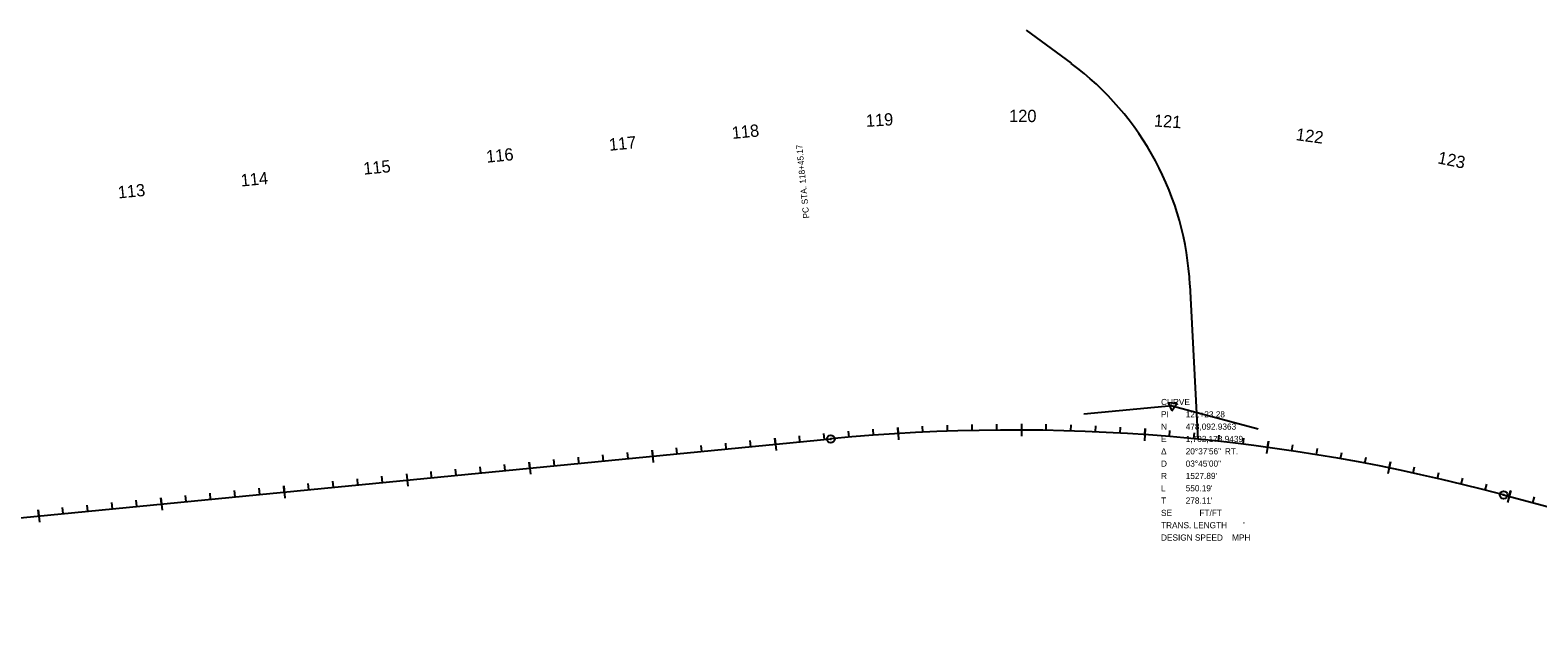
# Model space of a CAD drawing. Extents: x 1699999 to 1705087, y 475568 to 482652.
# Drawn here: x 1701253 to 1702475, y 477914 to 478398 of the extents above; entities that cross this region are included whole.
import ezdxf

# ---------------------------------------------------------------- set-up
doc = ezdxf.new("R2010")
doc.units = 0
for name, color, linetype in [('Default', 7, 'Continuous'), ('DES - DTM - Boundary', 7, 'Continuous'), ('DES - DTM - Ground', 7, 'Continuous'), ('DES - DTM - Points - High', 7, 'Continuous'), ('DESIGN - TYPICAL - Guardrail', 7, 'Continuous'), ('TC_Aggregate', 7, 'Continuous')]:
    doc.layers.add(name, color=color, linetype=linetype)

msp = doc.modelspace()

# ---------------------------------------------------------------- linework, layer by layer
at = {"layer": 'Default'}
for p, q in [((1702060.6, 478397.7), (1702097, 478370.8)), ((1702193.2, 478190.9), (1702199.5, 478065.9)), ((1700487.6, 477928.5), (1701902.1, 478066)), ((1702447.5, 478020.6), (1702841.8, 477914.3))]:
    msp.add_line(p, q, dxfattribs=at)
for centre, radius, start, end in [((1701954.8, 478179), 238.7, 2.8647, 53.4569), ((1702049.9, 476545.3), 1527.9, 74.9193, 95.5514)]:
    msp.add_arc(centre, radius, start, end, dxfattribs=at)
at = {"layer": 'DES - DTM - Ground'}
for p, q in [((1702060.6, 478397.7), (1702097, 478370.8)), ((1702193.2, 478190.9), (1702199.5, 478065.9)), ((1700487.6, 477928.5), (1701902.1, 478066)), ((1702447.5, 478020.6), (1702841.8, 477914.3))]:
    msp.add_line(p, q, dxfattribs=at)
for centre, radius, start, end in [((1701954.8, 478179), 238.7, 2.8647, 53.4569), ((1702049.9, 476545.3), 1527.9, 74.9193, 95.5514)]:
    msp.add_arc(centre, radius, start, end, dxfattribs=at)
at = {"layer": 'DES - DTM - Points - High'}
for p, q in [((1701976.8, 478071.4), (1701976.5, 478076.4)), ((1701996.8, 478072.3), (1701996.6, 478077.2)), ((1702016.7, 478072.8), (1702016.6, 478077.8)), ((1702036.7, 478073.1), (1702036.7, 478078.1)), ((1702056.8, 478078.2), (1702056.7, 478068.2)), ((1702076.7, 478073), (1702076.8, 478077.9)), ((1702096.7, 478072.5), (1702096.9, 478077.5)), ((1702116.7, 478071.7), (1702116.9, 478076.7)), ((1701837.3, 478059.7), (1701836.8, 478064.7)), ((1701856.7, 478066.6), (1701857.7, 478056.7)), ((1701877.1, 478063.6), (1701876.6, 478068.6)), ((1701897, 478065.5), (1701896.5, 478070.5)), ((1701916.9, 478067.4), (1701916.5, 478072.4)), ((1701936.8, 478069), (1701936.5, 478074)), ((1701956.5, 478075.3), (1701957.1, 478065.4)), ((1702136.7, 478070.7), (1702137, 478075.7)), ((1702157, 478074.5), (1702156.3, 478064.5)), ((1702176.6, 478067.9), (1702177, 478072.9)), ((1702196.5, 478066.2), (1702197, 478071.1)), ((1702216.4, 478064.1), (1702217, 478069.1)), ((1702236.3, 478061.8), (1702236.9, 478066.7)), ((1702256.8, 478064.2), (1702255.4, 478054.3)), ((1701717.8, 478048.1), (1701717.4, 478053.1)), ((1701737.7, 478050.1), (1701737.3, 478055)), ((1701757.2, 478057), (1701758.1, 478047)), ((1701777.6, 478053.9), (1701777.1, 478058.9)), ((1701797.5, 478055.9), (1701797, 478060.8)), ((1701817.4, 478057.8), (1701816.9, 478062.7)), ((1702275.9, 478056.4), (1702276.6, 478061.3)), ((1702295.7, 478053.3), (1702296.5, 478058.2)), ((1702315.4, 478050), (1702316.3, 478054.9)), ((1701578.5, 478034.6), (1701578, 478039.5)), ((1701598.4, 478036.5), (1701597.9, 478041.5)), ((1701618.3, 478038.4), (1701617.8, 478043.4)), ((1701638.2, 478040.4), (1701637.7, 478045.3)), ((1701657.6, 478047.3), (1701658.6, 478037.3)), ((1701678, 478044.2), (1701677.5, 478049.2)), ((1701697.9, 478046.2), (1701697.5, 478051.1)), ((1702335.1, 478046.4), (1702336, 478051.3)), ((1702355.7, 478047.4), (1702353.7, 478037.6)), ((1702374.3, 478038.4), (1702375.3, 478043.3)), ((1701458.6, 478027.9), (1701459.5, 478018)), ((1701479, 478024.9), (1701478.5, 478029.9)), ((1701498.9, 478026.8), (1701498.4, 478031.8)), ((1701518.8, 478028.8), (1701518.3, 478033.7)), ((1701538.7, 478030.7), (1701538.2, 478035.7)), ((1701558.1, 478037.6), (1701559.1, 478027.7)), ((1702393.8, 478034), (1702394.9, 478038.9)), ((1702413.2, 478029.4), (1702414.4, 478034.2)), ((1702432.6, 478024.5), (1702433.9, 478029.3)), ((1701339.6, 478011.4), (1701339.1, 478016.3)), ((1701359, 478018.3), (1701360, 478008.3)), ((1701379.4, 478015.2), (1701379, 478020.2)), ((1701399.3, 478017.2), (1701398.9, 478022.1)), ((1701419.2, 478019.1), (1701418.8, 478024.1)), ((1701439.2, 478021), (1701438.7, 478026)), ((1702453.3, 478024.2), (1702450.7, 478014.5)), ((1702471.3, 478014.2), (1702472.6, 478019)), ((1701259.5, 478008.6), (1701260.5, 477998.6)), ((1701279.9, 478005.6), (1701279.4, 478010.5)), ((1701299.8, 478007.5), (1701299.3, 478012.4)), ((1701319.7, 478009.4), (1701319.2, 478014.4))]:
    msp.add_line(p, q, dxfattribs=at)
at = {"layer": 'DESIGN - TYPICAL - Guardrail'}
for p, q in [((1702056.8, 478078.2), (1702056.7, 478068.2)), ((1701857.2, 478061.7), (1701856.7, 478066.6)), ((1701956.8, 478070.4), (1701956.5, 478075.3)), ((1702156.7, 478069.5), (1702157, 478074.4)), ((1702256.1, 478059.2), (1702256.8, 478064.2)), ((1701757.7, 478052), (1701757.2, 478056.9)), ((1701658.1, 478042.3), (1701657.6, 478047.3)), ((1702354.7, 478042.5), (1702355.7, 478047.4)), ((1701459.1, 478023), (1701458.6, 478027.9)), ((1701558.1, 478037.6), (1701559.1, 478027.6)), ((1701359.5, 478013.3), (1701359, 478018.2)), ((1702452, 478019.4), (1702453.2, 478024.2)), ((1701260, 478003.6), (1701259.5, 478008.6))]:
    msp.add_line(p, q, dxfattribs=at)
for centre, radius in [((1701902.1, 478066), 3.14), ((1701902.1, 478066), 0.33), ((1702447.5, 478020.6), 3.14), ((1702447.5, 478020.6), 0.33)]:
    msp.add_circle(centre, radius, dxfattribs=at)
at = {"layer": 'TC_Aggregate'}
for q in [(1702107.3, 478086), (1702178.9, 478092.9), (1702248.5, 478074.2)]:
    msp.add_line((1702178.9, 478092.9), q, dxfattribs=at)
msp.add_lwpolyline([(1702178.6, 478088.8), (1702182.7, 478094.7), (1702175.5, 478095.3)], close=True, dxfattribs=at)

# ---------------------------------------------------------------- texts
at = {"layer": 'DES - DTM - Boundary'}
for s, p in [('118+45.17', (1701882, 478273.5)), (' STA. ', (1701883.8, 478254.8)), ('PC', (1701884.7, 478245.2))]:
    msp.add_text(s, height=4.98, rotation=95.5514, dxfattribs=at).set_placement(p)
for s, p in [('CURVE    ', (1702169.8, 478093.5)), ('PI', (1702169.8, 478083.5)), ('121+23.28', (1702189.8, 478083.5)), ('N', (1702169.8, 478073.5)), ('478,092.9363', (1702189.8, 478073.5)), ('E', (1702169.8, 478063.5)), ('1,702,178.9439', (1702189.8, 478063.5)), ('Δ', (1702169.8, 478053.5)), ('20°37\'56"', (1702189.8, 478053.5)), (' RT.', (1702219.7, 478053.5)), ('D', (1702169.8, 478043.5)), ('03°45\'00"', (1702189.8, 478043.5)), ('R', (1702169.8, 478033.5)), ('L', (1702169.8, 478023.5)), ("550.19'", (1702189.8, 478023.5)), ("1527.89'", (1702189.8, 478033.5)), ('T', (1702169.8, 478013.5)), ("278.11'", (1702189.8, 478013.5)), ('SE', (1702169.8, 478003.5)), ('      FT/FT', (1702189.8, 478003.5)), ("TRANS. LENGTH       '", (1702169.8, 477993.5)), ('DESIGN SPEED    MPH', (1702169.8, 477983.5))]:
    msp.add_text(s, height=5, dxfattribs=at).set_placement(p)
at = {"layer": 'DES - DTM - Points - High'}
for s, rotation, p in [('120', 359.7453, (1702046.6, 478323.2)), ('118', 5.5514, (1701822.3, 478309.4)), ('119', 3.4953, (1701930.8, 478319.2)), ('121', 355.9953, (1702163.8, 478319.6)), ('117', 5.5514, (1701722.7, 478299.8)), ('122', 352.2453, (1702278.7, 478308.5)), ('116', 5.5514, (1701623.2, 478290.1)), ('123', 348.4953, (1702393.5, 478289.7)), ('115', 5.5514, (1701523.6, 478280.4)), ('113', 5.5514, (1701324.6, 478261.1)), ('114', 5.5514, (1701424.2, 478270.8))]:
    msp.add_text(s, height=9.96, rotation=rotation, dxfattribs=at).set_placement(p)
at = {"layer": 'DESIGN - TYPICAL - Guardrail'}
for s, rotation, p in [('120', 359.7453, (1702046.6, 478323.2)), ('115', 5.5514, (1701523.6, 478280.4))]:
    msp.add_text(s, height=9.96, rotation=rotation, dxfattribs=at).set_placement(p)

doc.saveas('drawing.dxf')
